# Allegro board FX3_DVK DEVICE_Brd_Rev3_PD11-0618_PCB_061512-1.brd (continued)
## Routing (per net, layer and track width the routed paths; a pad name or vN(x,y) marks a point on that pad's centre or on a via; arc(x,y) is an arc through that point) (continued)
CTL1: length 73.1
  TOP w0.279: J77.51 7.57,68.83 7.52,68.78 v1(7.48,68.78)
  TOP w0.381: J1.23 v1(25.52,61.45)
  TOP w0.483: v1(50.44,63.28) 51.24,64.07 R222.2
  SIG1#3 w0.127: v1(7.48,68.78) 7.1,68.41 5.08,68.41 4.75,68.74 4.75,69.06 5,69.32 7.88,69.32 8.47,68.73 8.47,66.79 8.07,66.39 4.75,66.39 4.23,65.87 4.23,64.42 4.99,63.67 6.95,63.67 9.53,66.24 10.67,66.24 11.04,65.87 12.44,64.46 14.17,62.74 24.23,62.74 24.68,62.28 24.68,62.28 v1(25.52,61.45) 25.52,61.44 25.53,61.44 25.79,61.71 29.24,61.71 29.61,62.08 32.98,62.08 33.82,61.24 33.82,59.79 34.5,59.11 45.81,59.11 49.02,62.32 50.13,62.32 50.44,62.63 v1(50.44,63.28)
CTL2: length 71.7
  TOP w0.279: J77.55 7.74,67.83 7.55,68.02 v1(7.53,68.02)
  TOP w0.381: J1.25 23.91,60.81 23.61,61.11 v1(23.61,61.57)
  SIG1#3 w0.127: v1(7.53,68.02) 7.82,68.02 8.04,67.8 8.04,66.97 7.89,66.82 4.58,66.82 3.8,66.05 3.8,64.24 3.82,64.22 3.82,64.21 5.38,62.65 11.27,62.65 13.12,60.81 15.05,60.81 16.11,61.87 17.78,61.87 18.28,61.37 21.71,61.37 22.22,61.87 23.3,61.87 23.6,61.57 v1(23.61,61.57)
  SIG2#6 w0.127: v1(49.74,64.4) 49.81,64.4 49.81,64.41 50.41,64.41 50.9,63.92 50.9,62.6 50.63,62.33 48.79,62.33 47.49,63.63 34.64,63.63 32.27,66 32.27,66.45 31.01,67.71 30.03,67.71 29.13,66.81 29.13,66.8 29.08,66.75 29.08,64.85 28.51,64.28 26.9,64.28 26.01,63.39 26.01,62.58 25.39,61.96 25.39,61.95 24.9,61.46 23.72,61.46 v1(23.61,61.57)
  BOTTOM w0.483: R223.2 50.43,65.02 49.81,64.4 v1(49.74,64.4)
CTL3: length 70.6
  TOP w0.203: J77.31 8.95,73.84 v1(10.4,73.84)
  TOP w0.381: v1(25.37,66.53) J1.7
  TOP w0.483: v1(53.96,69.36) 54.1,69.22 R224.2
  SIG1#3 w0.127: v1(25.37,66.53) 25.37,66.53 24.33,67.57 24.33,74.87 23.75,75.45 21.39,75.45 20.81,74.87 20.81,69.22 19.15,67.57 16.3,67.57 16.23,67.63 15.87,67.63 10.4,73.1 v1(10.4,73.84)
  SIG2#6 w0.127: v1(25.37,66.53) 25.37,66.59 24.73,67.23 24.73,69.08 26.15,70.51 26.39,70.51 26.39,70.51 29.66,70.51 29.75,70.42 34.07,70.42 36.55,67.94 42.81,67.94 43.33,67.42 48.06,67.42 49.17,68.53 51.08,68.53 52.09,69.54 52.61,69.54 52.98,69.54 53.16,69.36 v1(53.96,69.36)
CTL4: length 24.5
  TOP w0.203: v1(13.3,66.82) 13.31,66.83 J77.60
  SIG2#6 w0.127: J100.1 16.66,75.4 16.53,75.2 15.67,73.22 13.3,66.8 v1(13.3,66.82)
CTL4_LT: length 10.2
  TOP w0.483: J100.3 23.08,91.95 19.4,95.63 U45.3
CTL4_SW: length 49.3
  TOP w0.381: v1(34.44,66.9) 34.44,66.55 32.51,64.62 J1.14
  TOP w0.483: v1(54.01,65.28) 54.39,65.28 54.77,65.66 R225.2
  SIG1#3 w0.127: J100.2 25.66,87.29 v1(34.44,66.9)
  SIG2#6 w0.127: v1(54.01,65.28) 54,65.27 53.46,65.27 53.05,65.29 50.7,66.17 49.78,66.31 49.53,66.32 v1(34.44,66.9)
CTL5: length 68.5
  TOP w0.279: v1(11.08,70.77) 11.07,70.78 11.07,70.97 10.69,71.35 10.69,71.38 10.23,71.83 J77.39
  TOP w0.381: J1.13 23.59,64.62 v1(23.45,64.76)
  TOP w0.483: v1(49.82,69.55) 49.87,69.6 R226.2
  SIG1#3 w0.127: v1(11.08,70.77) 11.22,70.77 13.07,68.92 13.07,68.91 13.34,68.65 13.34,68.65 16.61,65.39 19.36,65.39 21.67,67.69 21.67,73.35 22.06,73.75 23.1,73.75 23.45,73.4 v1(23.45,64.76)
  SIG2#6 w0.127: v1(49.82,69.55) 49.58,69.55 49.41,69.38 47.89,67.86 43.51,67.86 42.99,68.37 36.73,68.37 34.25,70.85 29.93,70.85 29.84,70.95 26.21,70.95 26.21,70.94 25.97,70.94 24.19,69.16 24.19,68.73 24.19,67.3 23.45,66.56 v1(23.45,64.76)
CTL6: length 72.5
  TOP w0.279: J77.45 v1(7.48,70.33)
  TOP w0.381: J1.19 v1(25.52,62.72)
  TOP w0.483: v1(50.55,65.73) 50.89,65.73 51.2,66.04 R227.2
  SIG1#3 w0.127: v1(50.55,65.73) 50.55,64.58 49.58,63.62 48.79,63.62 45.88,60.71 45.28,60.71 34.96,60.71 33.16,62.51 30.69,62.51 29.5,63.7 27.5,63.7 26.51,62.72 v1(25.52,62.72) 24.86,62.72 24.41,63.17 14.35,63.17 12.91,64.6 12.91,64.61 10.79,66.73 10.79,66.73 9.98,67.54 8.9,68.62 8.9,68.91 8.29,69.52 8.06,69.75 3.07,69.75 1.76,71.07 1.76,74.43 2.21,74.88 3.63,74.88 4.14,74.37 4.14,72.16 5.19,71.11 6.7,71.11 v1(7.48,70.33)
CTL7: length 71.4
  TOP w0.279: J77.37 10.45,72.33 11.21,71.58 v1(11.21,71.58)
  TOP w0.381: v1(25.82,64.79) 25.35,65.26 J1.11
  SIG1#3 w0.127: v1(25.82,64.79) 25.82,64.75 25.53,64.46 24.28,64.46 23.89,64.85 23.89,74.67 23.58,74.99 21.54,74.99 21.24,74.69 21.24,67.87 19.19,65.82 16.81,65.82 15.62,67 15.62,67 11.22,71.4 11.22,71.57 v1(11.21,71.58)
  SIG2#6 w0.127: v1(25.82,64.79) 26.07,64.54 26.55,64.54 27.1,65.09 27.1,68.29 27.59,68.77 28.51,68.77 29.14,68.14 30.83,68.14 31.19,68.14 31.95,67.39 31.95,67.39 32.7,66.63 32.7,66.18 34.07,64.81 48.01,64.81 49.97,62.85 v1(49.97,62.79)
  BOTTOM w0.483: v1(49.97,62.79) 50.1,62.65 50.7,62.65 51.24,63.19 R228.2
CTL8: length 62.6
  TOP w0.279: v1(9.97,65.78) 10.44,66.25 10.44,69 10.1,69.34 9.2,69.34 9.2,69.33 J77.49
  TOP w0.381: v1(27.18,61.22) 27.09,61.32 27.05,61.32 26.29,62.08 J1.21
  SIG1#3 w0.127: v1(9.97,65.78) 9.97,65.78 9.28,65.09 9.28,63.8 9.99,63.09 11.45,63.09 12.23,62.3 23.12,62.3 23.51,62.3 24.06,61.76 24.82,60.99 26.95,60.99 v1(27.18,61.22)
  SIG2#6 w0.127: v1(50.33,54.74) 50.33,54.05 49.91,53.62 48.13,53.62 47.49,54.26 47.49,55.68 49.14,57.33 49.14,58.34 48.96,58.53 47.44,58.53 45.1,60.87 33.06,60.87 32.85,60.66 31.71,60.66 30.96,61.4 28.79,61.4 28.61,61.22 v1(27.18,61.22)
  BOTTOM w0.483: R229.2 v1(50.33,54.74)
CTL9: length 73.6
  TOP w0.279: J77.41 10.1,71.33 10.35,71.08 10.35,70.51 10.4,70.47 10.4,70.37 v1(10.42,70.35)
  TOP w0.381: J1.15 v1(25.52,63.99)
  TOP w0.483: R230.2 54.52,67.16 v1(54.14,67.16)
  SIG1#3 w0.127: v1(54.14,67.16) 54.14,67.02 53.36,66.24 52.26,66.24 51.35,67.15 50.37,67.15 50.37,67.16 50,67.16 49.99,67.15 49.98,67.15 49.71,66.88 49.71,66.33 44.96,61.57 44.92,61.57 44.6,61.57 35.41,61.57 33.54,63.44 31.01,63.44 30.07,64.38 29.1,65.35 29.1,65.71 28.56,66.25 26.8,66.25 26.39,65.84 26.39,64.71 25.67,63.99 v1(25.52,63.99) 25.5,63.99 25.46,64.03 14.72,64.03 11.08,67.67 11.07,67.67 10.59,68.15 9.77,68.98 9.77,69.27 8.71,70.32 8.71,72.37 7.43,73.66 7.43,75.97 7.75,76.29 8.64,76.29 9.3,75.63 9.3,75.63 9.96,74.97 9.96,70.81 v1(10.42,70.35)
CTL10: length 72.5
  TOP w0.279: J77.43 7.7,70.83 v1(7.46,71.07)
  TOP w0.381: J1.17 v1(25.56,63.35)
  TOP w0.483: R231.2 51.08,67.82 50.52,67.26 50.52,67.26 50.19,66.93 50.19,66.92 50.18,66.91 v1(50.18,66.71)
  SIG1#3 w0.127: v1(7.46,71.07) 7.46,71.08 6.99,71.55 5.56,71.55 4.57,72.53 4.57,77.29 5.08,77.8 6.52,77.8 7,77.32 7,73.48 8.28,72.19 8.28,70.14 9.33,69.09 9.33,68.8 10.29,67.85 10.64,67.49 11.04,67.09 14.53,63.6 24.59,63.6 24.83,63.35 v1(25.56,63.35) 26.53,63.35 27.32,64.14 29.7,64.14 29.89,63.94 30.9,62.94 33.34,62.94 35.14,61.14 44.42,61.14 45.22,61.14 48.94,64.85 49.55,64.85 50.1,65.4 50.1,66.63 v1(50.18,66.71)
CTL11: length 73
  TOP w0.279: J77.54 15.93,68.33 v1(16.04,68.44)
  TOP w0.381: v1(32.44,63.88) 32.34,63.99 J1.16
  SIG1#3 w0.127: v1(54.09,68.05) 53.88,67.85 53.39,67.35 51.69,67.35 51.51,67.53 50.53,67.53 50.52,67.54 49.84,67.54 49.84,67.53 49.83,67.53 49.33,67.04 49.33,66.72 49.33,66.56 44.96,62.19 36.6,62.19 35.48,63.31 35.48,64.38 34.68,65.18 33.06,65.18 32.44,64.56 v1(32.44,63.88) 31.2,63.88 29.53,65.55 29.53,66.02 29.42,66.13 28.87,66.68 25.93,66.68 25.61,67 25.61,67 25.35,67.26 25.35,67.26 24.8,67.82 24.8,77.28 22.25,79.83 18.92,79.83 17.77,78.67 17.77,76.12 20.37,73.52 20.37,69.43 19.6,68.66 16.28,68.66 16.06,68.44 v1(16.04,68.44)
  BOTTOM w0.483: v1(54.09,68.05) 54.36,68.33 R232.2
CTL12: length 70.6
  TOP w0.279: J77.57 7.5,67.33 v1(7.48,67.35)
  TOP w0.381: v1(22.52,61.34) 22.53,61.33 22.53,61.33 23.69,60.18 J1.27
  SIG1#3 w0.127: v1(22.52,61.34) 22.52,61.32 21.57,60.37 12.94,60.37 11.09,62.22 5.17,62.22 3.32,64.07 3.32,66.35 4.71,67.75 7.09,67.75 v1(7.48,67.35)
  SIG2#6 w0.127: v1(49.52,65.48) 49.52,65.48 49.29,65.24 34.25,65.24 33.13,66.36 33.13,66.81 32.38,67.56 32.38,67.57 31.37,68.58 31.37,68.58 30.65,68.58 30.65,68.58 29.7,68.58 29.06,69.22 27.08,69.22 26.67,68.81 26.67,66.29 22.52,62.14 v1(22.52,61.34)
  BOTTOM w0.483: v1(49.52,65.48) 49.52,67.08 49.54,67.09 49.54,67.11 51.14,68.71 R233.2
CVDDQ: length 4.9
  TOP w0.254: U1.B6 68,62.71 68,62.71 v2(68.24,62.95) ; X2.12 v1(75.44,54.38)
  TOP w0.508: R39.2 v3(74.04,75.82) ; R63.2 v3(11.1,106.35) ; R37.2 v3(69.72,75.82) ; R38.2 v3(71.75,75.82) ; R10.2 v3(9.47,101.8)
DQ0: length 67.8
  TOP w0.254: v1(13.29,59.91) 13.37,59.83 J77.68
  TOP w0.381: v1(23.01,59.46) 23.09,59.54 J1.29
  SIG1#3 w0.127: v1(49.97,55.69) 48.82,54.54 33.89,54.54 33.29,55.14 28.89,55.14 28.12,54.37 25.55,54.37 24.81,55.11 24.81,58.12 23.47,59.46 v1(23.01,59.46) 16.91,59.46 16.77,59.6 15.95,59.6 15.61,59.26 15.61,58 15.96,57.65 15.96,57.65 16.22,57.39 16.22,57.39 16.38,57.23 20.46,57.23 21.22,56.47 21.22,54.41 20.19,53.39 14.71,53.39 13.71,54.39 13.71,59.5 v1(13.29,59.91)
  BOTTOM w0.483: v1(49.97,55.69) 50.17,55.69 51.24,56.76 R5.2
DQ1: length 67
  TOP w0.254: v1(16.89,58.33) 16.88,58.34 14.68,58.34 J77.74
  TOP w0.381: v1(29.74,60.92) 29.74,61.16 29.74,61.16 29.74,62.31 30.78,63.35 J1.18
  SIG1#3 w0.127: v1(29.74,60.92) 29.74,60.91 29.74,59.35 29.01,58.61 26.37,58.61 25.54,57.78 25.54,56.46 26.38,55.63 33.41,55.63 34.07,54.97 48.54,54.97 49.71,56.14 50.41,56.14 50.78,55.77 50.78,55.06 51.11,54.72 52.29,54.72 52.62,55.05 52.62,58.52 52.14,59 50.98,59 50.53,58.56 50.53,57.13 v1(50.44,57.03)
  SIG2#6 w0.127: v1(16.89,58.33) 17.47,57.76 21.71,57.76 22.45,57.02 25.8,57.02 27.67,58.89 28.26,58.89 29.74,60.37 v1(29.74,60.92)
  BOTTOM w0.483: v1(50.44,57.03) 50.44,57.15 51.08,57.78 R205.2
DQ2: length 71.5
  TOP w0.254: J77.76 v1(16.4,57.83)
  TOP w0.381: v1(30.32,60.95) 30.32,60.96 30.32,62.06 30.97,62.72 J1.20
  TOP w0.483: R206.2 54.66,60.33 53.89,59.55 v1(53.84,59.55)
  SIG1#3 w0.127: v1(53.84,59.55) 49.41,59.55 49.04,59.18 49.04,59.17 47.34,57.47 47.34,57.46 46.93,57.05 46.92,57.05 46.22,56.35 34.02,56.35 33.37,57 33.35,57 33.34,57.01 32.95,57.01 32,56.06 29.39,56.06 29.08,56.37 29.08,57.23 29.08,57.23 29.08,58 29.46,58.38 30.17,58.38 30.49,58.06 30.49,57.01 30.72,56.77 31.4,56.77 31.66,57.03 31.66,57.79 31.81,57.94 32.7,57.94 33.05,58.28 33.05,58.82 32.76,59.11 30.45,59.11 30.19,59.37 30.19,59.83 30.44,60.07 32.44,60.07 32.72,60.36 32.72,60.75 32.46,61.01 30.48,61.01 30.42,60.95 v1(30.32,60.95)
  SIG2#6 w0.127: v1(30.32,60.95) 30.32,60.95 30.8,60.95 31.41,60.34 31.41,60.05 31.06,59.69 29.67,59.69 29.43,59.45 29.43,59.04 29.62,58.85 30.26,58.85 30.37,58.74 30.37,58.26 28.71,56.59 22.27,56.59 21.53,57.33 19.85,57.33 19.85,57.33 16.91,57.33 16.42,57.82 16.41,57.82 v1(16.4,57.83)
DQ3: length 73.3
  TOP w0.254: v1(16.15,59.14) 15.95,59.33 J77.70
  TOP w0.381: J1.31 23.26,58.91 23.25,58.89 22.97,58.89 v1(22.95,58.86)
  SIG1#3 w0.127: v1(54.79,55.87) 54.79,55.33 53.84,54.38 52.99,54.38 52.72,54.11 33.71,54.11 33.11,54.71 29.09,54.71 28.31,53.93 26.41,53.93 26,53.53 26,51.9 26.35,51.55 33.29,51.55 33.6,51.25 33.6,49.62 33.28,49.31 24.87,49.31 24.28,49.9 24.28,57.84 23.26,58.86 v1(22.95,58.86) 20.01,58.86 19.29,58.13 18.02,58.13 17.13,59.03 16.73,59.03 16.26,59.03 v1(16.15,59.14)
  BOTTOM w0.483: v1(54.79,55.87) R207.2
DQ4: length 68.3
  TOP w0.279: v1(16.05,69.33) J77.50
  TOP w0.381: v1(30.66,65.14) 30.75,65.23 31,65.23 31.02,65.26 J1.12
  TOP w0.483: v1(50.08,57.69) 50.3,57.69 51.24,58.63 R208.2
  SIG1#3 w0.127: v1(30.66,65.14) 30.58,65.14 29.96,65.76 29.96,68.38 29.49,68.85 29.49,68.87 29.26,69.1 29.26,69.1 25.85,72.51 25.85,77.64 24.08,79.4 22.8,80.69 17.87,80.69 15.81,78.63 15.81,75 17.11,73.7 18.05,73.7 18.98,72.78 18.98,71.53 17.9,70.45 17.17,70.45 16.05,69.34 v1(16.05,69.33)
  SIG2#6 w0.127: v1(30.66,65.14) 30.66,62.45 32.02,61.09 32.67,61.09 32.92,61.33 45.25,61.33 47.62,58.96 49.63,58.96 50.1,58.49 50.1,58.07 50.08,58.05 v1(50.08,57.69)
DQ5: length 67.7
  TOP w0.254: J77.80 17.67,56.83 v1(18.06,56.45)
  TOP w0.381: v1(34.32,60.04) 34.32,60.03 34.13,59.84 33.07,59.84 32.73,60.18 J1.28
  SIG1#3 w0.127: v1(50.81,66.7) 51.11,66.4 51.11,64.6 49.71,63.2 48.98,63.2 45.4,59.62 34.74,59.62 v1(34.32,60.04)
  SIG2#6 w0.127: v1(18.06,56.45) 18.04,56.46 14.3,56.46 14.09,56.26 14.09,55.5 15.67,53.92 16.56,53.92 16.81,54.17 16.81,55.17 17.06,55.43 18.12,55.43 18.4,55.15 18.4,53.08 18.64,52.84 19.65,52.84 19.88,53.06 19.88,56.13 20.21,56.46 21.17,56.46 21.49,56.15 21.49,53.35 21.87,52.98 22.94,52.98 23.61,53.65 23.61,55.37 23.96,55.73 29.06,55.73 31.93,58.59 32.43,59.1 32.44,59.1 33.07,59.72 33.93,59.72 34.25,60.04 v1(34.32,60.04)
  BOTTOM w0.483: R209.2 51.04,66.93 50.82,66.71 50.81,66.71 50.81,66.7 v1(50.81,66.7)
DQ6: length 75.6
  TOP w0.254: J77.32 17.43,73.83 18.33,72.93 18.33,72.19 v1(18.1,71.95)
  TOP w0.381: v1(30.55,66.33) 30.74,66.53 J1.8
  SIG1#3 w0.127: v1(18.1,71.95) 16.37,71.95 13.51,74.81 13.51,79.33 16.31,82.13 22.58,82.13 30.18,74.53 30.18,69.77 30.56,69.39 30.56,66.34 v1(30.55,66.33)
  SIG2#6 w0.127: v1(54.1,57.64) 54.11,57.64 54.11,58.43 53.81,58.72 53.38,58.72 53.27,58.62 52.77,58.62 50.85,60.53 48.76,60.53 47.04,62.24 33.15,62.24 31.1,64.3 31.1,65.33 30.55,65.89 v1(30.55,66.33)
  BOTTOM w0.483: v1(54.1,57.64) 54.1,57.88 54.32,58.1 54.32,58.1 54.64,58.42 R210.2
DQ7: length 71.4
  TOP w0.203: v1(17.56,70.9) 17.54,70.9 17.44,71 17.44,71 17.1,71.33 J77.42
  TOP w0.381: v1(29.93,69.04) 29.93,66.1 30.26,65.78 30.29,65.78 30.31,65.75 30.78,65.75 30.92,65.89 J1.10
  TOP w0.483: R211.2 51.2,62.36 50.72,61.87 v1(50.43,61.87)
  SIG1#3 w0.127: v1(17.56,70.9) 17.73,70.9 18.54,71.71 18.54,72.6 17.87,73.27 16.43,73.27 15.14,74.57 15.14,78.78 17.48,81.12 22.98,81.12 26.28,77.82 26.28,72.69 27.27,71.71 27.27,71.71 29.93,69.05 v1(29.93,69.04)
  SIG2#6 w0.127: v1(29.93,69.04) 32.75,69.04 33.56,68.23 33.56,66.54 34.18,65.92 34.18,65.92 34.43,65.67 41.06,65.67 41.31,65.92 49.71,65.92 49.87,65.76 49.87,65.76 50.72,64.91 50.72,64.9 51.66,63.97 51.66,62.27 51.26,61.87 v1(50.43,61.87)
DQ8: length 75.7
  TOP w0.254: J77.66 16.02,60.33 16.04,60.32 16.68,60.32 v1(17.09,59.91)
  TOP w0.381: J1.24 32.25,61.45 v1(32.35,61.54)
  SIG1#3 w0.127: v1(32.35,61.54) 32.35,61.44 29.63,61.44 29.08,60.89 29.08,59.5 28.63,59.04 26.09,59.04 24.86,60.28 23.52,60.28 23.18,59.94 17.13,59.94 v1(17.09,59.91)
  SIG2#6 w0.127: v1(53.56,58.28) 52.6,57.32 52.6,49.68 50.04,47.11 47.06,47.11 45.44,48.74 45.44,52.37 46.31,53.24 50.6,53.24 50.99,53.63 50.99,58.79 50.39,59.39 48.17,59.39 45.75,61.81 32.62,61.81 32.35,61.54 v1(32.35,61.54)
  BOTTOM w0.483: v1(53.56,58.28) 53.56,58.37 54.25,59.06 54.26,59.06 54.32,59.11 54.32,59.11 54.64,59.44 R212.2
DQ9: length 70.4
  TOP w0.254: v1(10.42,54.33) J77.89
  TOP w0.381: J1.36 32.33,57.64 32.74,57.23 32.74,57.23 33.16,56.81 v1(33.16,56.57)
  SIG1#3 w0.127: v1(33.16,56.57) 33.19,56.57 33.92,55.84 47.25,55.84 49.66,58.24 v1(49.66,58.25)
  SIG2#6 w0.127: v1(33.16,56.57) 35.55,56.57 36.65,55.47 36.65,55.25 36.65,55.24 36.65,49.04 36.12,48.5 33.65,48.5 33.01,49.15 33.01,53.74 32,54.75 31.16,54.75 27.19,50.79 27.19,50.79 26.58,50.17 12.56,50.17 10.42,52.31 v1(10.42,54.33)
  BOTTOM w0.483: R213.2 51.15,59.56 49.87,58.29 49.75,58.29 49.71,58.25 v1(49.66,58.25)
DQ10: length 75.1
  TOP w0.254: J77.61 10.41,61.33 10.72,61.03 v1(10.72,61.03)
  TOP w0.381: v1(23.39,57.48) 23.39,57.89 23.77,58.27 J1.33
  TOP w0.483: v1(53.77,61.3) 53.98,61.3 54.78,62.1 R214.2
  SIG1#3 w0.127: v1(10.72,61.03) 11.14,60.6 11.14,59.01 13.28,56.88 13.28,54.21 15.33,52.15 21.67,52.15 23.25,53.73 23.25,53.73 23.34,53.82 23.34,57.4 23.4,57.46 23.4,57.48 v1(23.39,57.48)
  SIG2#6 w0.127: v1(23.39,57.48) 23.39,57.88 22.86,58.41 22.28,58.41 21.72,58.98 21.72,60.07 22.05,60.41 24.18,60.41 24.4,60.19 24.4,58.84 24.85,58.39 25.93,58.39 26.29,58.75 26.29,60.96 26.73,61.41 27,61.67 28.44,61.67 29.94,63.17 29.94,66.35 30.37,66.78 30.72,66.78 31.4,66.1 31.4,65.64 34.37,62.68 47.22,62.68 47.23,62.67 48.98,60.92 52.97,60.92 53.34,61.3 v1(53.77,61.3)
DQ11: length 75.6
  TOP w0.254: v1(11.01,56.28) 10.99,56.3 10.99,56.47 10.62,56.83 J77.79
  TOP w0.381: J1.30 32.63,59.54 32.85,59.32 33.66,59.32 34.51,58.47 v1(34.53,58.47)
  TOP w0.483: R215.2 54.66,63.88 54.26,63.48 v1(54.13,63.48)
  SIG1#3 w0.127: v1(54.13,63.48) 53.73,63.48 52.87,62.62 52.87,62.62 51.27,61.02 48.37,61.02 47.6,60.25 47.6,60.25 45.84,58.5 34.56,58.5 v1(34.53,58.47)
  SIG2#6 w0.127: v1(11.01,56.28) 11.01,56.27 11.3,55.98 11.3,52.65 12.41,51.54 26.35,51.54 26.36,51.54 26.72,51.54 30.8,55.62 30.8,55.63 32.97,57.8 32.98,57.8 33.09,57.91 33.12,57.91 33.12,57.91 33.49,57.91 33.49,57.91 34.05,57.91 34.06,57.91 34.42,57.91 34.43,57.91 35.47,57.91 36.18,57.2 36.18,57.19 37.52,55.86 37.52,55.5 37.52,53.59 37.87,53.23 39.38,53.23 39.78,53.63 39.78,55.61 36.75,58.64 34.7,58.64 v1(34.53,58.47)
DQ12: length 72.3
  TOP w0.254: J77.71 10.27,58.83 11.24,57.86 v1(11.24,57.38)
  TOP w0.381: J1.35 25.25,57.64 25.6,57.29 v1(25.6,55.19)
  TOP w0.483: v1(48.7,58.08) 48.71,58.1 48.71,58.16 51.1,60.55 51.21,60.55 R216.2
  SIG2#6 w0.127: v1(48.7,58.08) 48.54,57.92 48.54,57.91 44.23,53.6 44.23,46.7 43.59,46.06 41.94,46.06 41.27,46.72 41.27,55.34 37.07,59.54 34.37,59.54 33.83,59.01 32.97,59.01 32.62,58.66 32.61,58.66 29.14,55.19 v1(25.6,55.19) 25.6,55.03 22.98,52.41 16.57,52.41 12.1,56.87 12.1,56.91 11.62,57.38 v1(11.24,57.38)
DQ13: length 72.6
  TOP w0.254: v1(10.35,56.28) 10.35,56.28 10.29,56.33 J77.81
  TOP w0.381: J1.32 32.53,58.91 32.64,58.79 32.92,58.79 33.68,58.03 33.69,58.03 34.24,57.48 v1(34.24,57.47)
  SIG1#3 w0.127: v1(48.7,60.08) 48.7,60.07 45.9,57.27 34.45,57.27 34.25,57.47 v1(34.24,57.47)
  SIG2#6 w0.127: v1(34.24,57.47) 35.29,57.47 36,56.76 37.08,55.68 37.08,53.41 37.69,52.8 38.05,52.8 39.2,52.8 39.2,52.8 39.56,52.8 40.21,53.45 40.21,55.79 36.9,59.1 34.53,59.1 34.01,58.58 33.15,58.58 32.8,58.23 32.79,58.23 30.37,55.81 30.37,55.8 26.54,51.97 14.71,51.97 12.31,54.38 12.31,55.99 11.95,56.34 11.51,56.79 10.86,56.79 v1(10.35,56.28)
  BOTTOM w0.483: R217.2 51.23,61.47 49.85,60.08 48.7,60.08 v1(48.7,60.08)
DQ14: length 75.6
  TOP w0.254: J77.65 10.26,60.33 10.44,60.51 v1(10.45,60.51)
  TOP w0.381: J1.37 23.81,57 23.72,56.91 23.15,56.91 22.75,57.32 v1(22.75,57.9)
  SIG1#3 w0.127: v1(22.75,57.9) 22.88,58.03 23.48,58.03 23.84,57.66 23.84,53.72 23.68,53.55 23.68,53.55 21.85,51.72 14.98,51.72 12.57,54.13 12.57,56.89 10.53,58.93 10.53,58.93 9.95,59.51 9.95,60.06 10.4,60.51 v1(10.45,60.51)
  SIG2#6 w0.127: v1(53.9,62.59) 53.83,62.65 53.02,62.65 51.67,61.31 49.2,61.31 47.38,63.13 34.53,63.13 31.84,65.82 31.84,66.28 30.9,67.21 30.54,67.21 30.54,67.21 30.14,67.21 29.51,66.58 29.51,64.67 29.5,64.66 29.5,64.56 28.78,63.85 28.69,63.85 27.08,63.85 26.44,63.21 26.44,61.73 26.3,61.59 26.3,61.59 26.29,61.57 25.62,60.9 21.93,60.9 21.07,60.04 21.07,59.01 21.89,58.19 21.89,58.19 22.18,57.9 v1(22.75,57.9)
  BOTTOM w0.483: R218.2 54.39,62.59 v1(53.9,62.59)
DQ15: length 73.9
  TOP w0.254: J77.83 10.11,55.83 10.25,55.68 v1(10.34,55.68)
  TOP w0.381: v1(33.31,57.47) 33.29,57.47 32.49,58.27 J1.34
  SIG1#3 w0.127: v1(53.9,60.41) 53.42,59.93 52.78,59.93 52.78,59.93 49.18,59.93 48.61,59.36 48.61,59.35 46.04,56.78 34.2,56.78 33.52,57.46 33.32,57.46 v1(33.31,57.47)
  SIG2#6 w0.127: v1(33.31,57.47) 33.3,57.47 33.21,57.39 33.21,57.39 32.69,56.87 32.69,56.2 32.99,55.9 35.61,55.9 36.22,55.29 36.22,49.85 35.87,49.5 33.69,49.5 33.44,49.75 33.44,53.92 32.17,55.19 30.98,55.19 26.9,51.11 26.18,51.11 12.23,51.11 10.87,52.48 10.87,55.18 10.36,55.68 v1(10.34,55.68)
  BOTTOM w0.483: v1(53.9,60.41) 54.7,61.21 R219.2
DQ16: length 73
  TOP w0.254: v1(16.48,68.01) 16.45,68.01 16.27,67.83 J77.56
  TOP w0.381: v1(42.28,76.47) J2.11
  SIG2#6 w0.127: v1(16.48,68.01) 16.76,68.01 18.57,69.81 18.57,72.66 25.64,79.74 27.93,79.74 28.3,80.11 28.3,82.52 29.08,83.3 30.44,83.3 31.07,82.67 31.07,79.41 31.33,79.16 32.85,79.16 33.11,79.42 33.11,83.52 33.42,83.82 34.15,83.82 34.54,83.43 34.54,79.45 34.83,79.16 35.89,79.16 36.16,79.43 36.16,82.06 36.39,82.29 37.13,82.29 37.82,81.61 37.82,78.26 39.84,76.23 42.04,76.23 v1(42.28,76.47) 43.07,75.68 43.07,74.33 44.21,73.19 44.58,72.83 50.52,72.83 50.69,72.66 53.79,72.66 v1(53.97,72.83)
  BOTTOM w0.483: v1(53.97,72.83) 54,72.8 54,72.78 54.79,71.98 R6.2
DQ17: length 72.5
  TOP w0.254: J77.85 7.52,55.33 v1(7.42,55.43)
  TOP w0.381: v1(38.71,71.24) 38.86,71.39 J2.27
  SIG1#3 w0.127: v1(38.71,71.24) 38.44,70.96 38.44,69.41 42.71,65.14 45.8,65.14 46.66,66 47.51,66.85 47.52,66.85 47.77,67.1 47.78,67.1 49.35,68.68 49.35,68.68 51.64,68.68 52.51,69.54 53.19,69.54 53.7,70.05 v1(53.7,70.28)
  SIG2#6 w0.127: v1(7.42,55.43) 7.3,55.55 7.3,55.89 7.57,56.16 7.87,56.16 11.18,59.46 11.18,60.8 11.68,61.3 15.14,61.3 17.34,63.5 21.2,67.35 21.2,67.36 22.03,68.19 22.03,71.23 27.02,76.22 28.95,76.22 29.46,75.71 29.47,75.71 30.13,75.04 30.13,73.7 30.82,73.01 36,73.01 37.78,71.24 v1(38.71,71.24)
  BOTTOM w0.483: v1(53.7,70.28) 53.87,70.1 R12.2
DQ18: length 73.4
  TOP w0.254: J77.73 7.81,58.33 7.64,58.5 v1(7.04,58.5)
  TOP w0.381: J2.19 42.23,73.93 v1(42.45,73.71)
  TOP w0.483: R13.2 54.79,72.75 54.25,72.21 v1(53.55,72.21)
  SIG2#6 w0.127: v1(7.04,58.5) 7.21,58.5 8,59.3 8,61.84 11.08,64.92 16.13,64.92 18.71,67.49 20,68.78 20,68.79 20.3,69.09 20.3,71.95 26.3,77.95 30.08,77.95 30.59,77.44 30.61,77.44 30.61,77.43 35,77.43 37.98,74.46 40.03,74.46 40.04,74.46 40.4,74.46 41.71,74.46 v1(42.45,73.71) 42.47,73.69 42.47,71.71 44.35,69.83 45.76,69.83 46.09,70.17 46.09,71.73 46.32,71.96 47,71.96 47.24,71.73 47.24,69.17 47.66,68.74 48.23,68.74 49.03,69.54 49.03,70.39 49.36,70.71 50.97,70.71 52.48,72.22 53.54,72.22 v1(53.55,72.21)
DQ19: length 70.6
  TOP w0.254: J77.87 v1(7.37,54.83)
  TOP w0.381: J2.29 40.13,70.75 v1(39.97,70.59)
  SIG1#3 w0.127: v1(54.17,74.72) 53.21,73.76 52.9,73.76 52.3,73.17 52.3,71.01 52.08,70.78 52.07,70.78 51.28,69.99 49.44,69.99 47.16,67.71 47.15,67.71 46.3,66.87 46.3,66.87 45.99,66.56 43.62,66.56 39.97,70.21 v1(39.97,70.59)
  SIG2#6 w0.127: v1(7.37,54.83) 7.46,54.83 7.87,55.24 7.87,55.54 11.72,59.39 13.82,59.39 15.12,60.69 15.14,60.69 15.39,60.94 15.39,60.94 17.77,63.32 21.63,67.18 21.63,67.18 22.46,68.01 22.46,68.37 22.46,70.93 25.81,74.28 25.81,74.29 27.32,75.79 28.77,75.79 29.28,75.27 29.28,75.27 29.7,74.85 29.7,73.52 30.65,72.58 35.56,72.58 37.56,70.58 39.85,70.58 39.87,70.59 v1(39.97,70.59)
  BOTTOM w0.483: R14.2 54.34,74.55 v1(54.17,74.72)
DQ20: length 69.8
  TOP w0.254: J77.77 7.41,57.33 7.39,57.35 v1(7.37,57.35)
  TOP w0.381: J2.23 42.1,72.66 43.3,71.46 v1(43.3,70.2)
  SIG1#3 w0.127: v1(43.3,70.2) 43.3,70.19 43.85,69.64 43.85,68.42 44.4,67.87 45.33,67.87 45.9,68.44 45.9,68.45 48.67,71.22 49.6,71.22 v1(49.74,71.36)
  SIG2#6 w0.127: v1(7.37,57.35) 7.37,57.35 8.92,58.9 8.92,61 10.66,62.75 15.37,62.75 16.48,63.86 19.54,66.92 19.54,66.92 21.16,68.55 21.16,71.59 26.66,77.09 29.72,77.09 30.23,76.57 30.25,76.57 30.25,76.57 34.58,76.57 37.57,73.58 38.65,73.58 38.94,73.29 38.94,72.46 39.25,72.15 39.86,72.15 40.21,72.5 40.21,73.08 40.66,73.53 41.5,73.53 42.04,72.99 42.04,71.46 v1(43.3,70.2)
  BOTTOM w0.483: R15.2 51.22,70.5 50.12,70.5 49.74,70.89 v1(49.74,71.36)
DQ21: length 70.5
  TOP w0.254: J77.75 7.61,57.83 7.52,57.92 v1(7.06,57.92)
  TOP w0.381: v1(40.22,74.01) 40.22,73.8 40.72,73.29 J2.21
  SIG1#3 w0.127: v1(40.22,74.01) 40.25,73.98 41.11,73.98 41.65,74.53 42.52,74.53 42.9,74.15 42.9,73.55 43.11,73.34 43.74,73.34 43.94,73.54 43.94,74.65 44.26,74.97 45.27,74.97 45.77,74.47 45.91,74.34 45.91,74.33 46.88,73.35 48.13,73.35 49.63,74.85 49.63,75.57 49.63,75.57 49.63,76.96 49.97,77.3 51.21,77.3 52.19,76.57 52.49,76.49 52.59,76.44 v1(53.87,76.1)
  SIG2#6 w0.127: v1(40.22,74.01) 37.81,74.01 34.82,77 30.43,77 30.43,77 30.41,77 29.9,77.52 26.48,77.52 20.73,71.77 20.73,68.91 20.43,68.61 20.43,68.6 19.14,67.31 15.15,63.33 10.1,63.33 8.49,61.71 8.49,59.17 7.24,57.92 v1(7.06,57.92)
  BOTTOM w0.483: v1(53.87,76.1) 54.41,75.56 R16.2
DQ22: length 68.4
  TOP w0.254: v1(7.4,59.33) 7.66,59.33 J77.69
  TOP w0.381: v1(40.43,74.9) 40.43,74.85 40.72,74.56 J2.17
  SIG2#6 w0.127: v1(50.63,72.11) 50.34,72.39 44.4,72.39 43.73,73.06 43.73,73.06 42.9,73.89 42.9,73.9 42.64,74.15 42.64,74.16 41.9,74.9 v1(40.43,74.9) 38.32,74.9 35.36,77.86 35.19,77.86 35.18,77.86 30.79,77.86 30.79,77.87 30.77,77.87 30.23,78.4 26.14,78.4 19.87,72.13 19.87,69.27 18.27,67.68 18.27,67.67 15.95,65.35 11.75,65.35 11.09,65.35 11.09,65.35 10.9,65.35 7.4,61.85 7.4,60.65 6.99,60.24 6.03,60.24 5.8,60.46 5.8,60.95 5.36,61.39 4.44,61.39 4,60.95 4,59.79 4.74,59.05 7.12,59.05 v1(7.4,59.33)
  BOTTOM w0.483: v1(50.63,72.11) 50.76,72.24 51.21,72.24 R17.2
DQ23: length 68
  TOP w0.254: v1(10.46,59.83) 10.45,59.83 8.95,59.83 J77.67
  TOP w0.381: v1(40.62,71.96) 40.68,72.02 J2.25
  TOP w0.483: v1(50.45,71.36) 50.53,71.36 50.55,71.37 R18.2
  SIG1#3 w0.127: v1(50.45,71.36) 50.44,71.36 49.99,71.8 49.23,71.8 49.04,71.62 48.19,71.62 46.4,69.83 44.31,69.83 43.43,70.71 41.34,70.71 40.62,71.43 v1(40.62,71.96)
  SIG2#6 w0.127: v1(10.46,59.83) 10.46,59.85 10.01,60.3 10.01,60.98 10.86,61.82 15.06,61.82 16.91,63.68 19.97,66.74 19.97,66.75 21.6,68.37 21.6,71.41 26.84,76.65 29.12,76.65 29.64,76.14 29.65,76.14 30.57,75.22 30.57,74.68 30.57,74.16 31.01,73.71 31.72,73.71 32.12,74.12 32.12,75.93 32.3,76.11 33.15,76.11 33.33,75.93 33.33,73.65 33.54,73.44 34.15,73.44 34.36,73.65 34.36,75.33 34.6,75.57 34.97,75.57 35.46,75.08 35.46,73.86 35.87,73.44 36.18,73.44 37.91,71.71 39.07,71.71 39.68,71.1 41.02,71.1 41.19,71.26 41.19,71.85 41.01,72.03 40.68,72.03 v1(40.62,71.96)
DQ24: length 64.7
  TOP w0.254: J77.78 14.68,57.33 17.73,57.33 v1(19.08,58.68)
  TOP w0.381: v1(40.96,66.2) 41.08,66.33 41.12,66.33 41.39,66.6 J2.37
  SIG1#3 w0.127: v1(40.96,66.2) 40.99,66.2 42.57,64.63 45.9,64.63 46.84,65.57 46.85,65.57 47.7,66.42 47.7,66.42 47.95,66.67 47.96,66.67 48.57,67.28 48.57,67.36 49.51,68.3 49.52,68.3 49.52,68.3 50.84,68.3 50.84,68.3 51.9,68.3 52.23,68.63 53.39,68.63 53.63,68.88 54.13,68.88 54.66,69.41 54.66,77.68 v1(53.99,78.35)
  SIG2#6 w0.127: v1(40.96,66.2) 40.84,66.2 34.51,66.2 34,66.72 34,68.05 34,68.43 32.95,69.48 29.47,69.48 29.3,69.65 26.81,69.65 26.24,69.08 26.24,68.44 26.24,66.48 23.44,63.67 23.44,63.67 19.08,59.31 v1(19.08,58.68)
  BOTTOM w0.483: R20.2 54.62,77.6 53.99,78.23 v1(53.99,78.35)
DQ25: length 66
  TOP w0.254: J77.72 12.5,58.83 v1(12.4,58.94)
  TOP w0.381: J2.35 v1(42.32,68.85)
  SIG1#3 w0.127: v1(50.45,73.9) 50.66,73.9 51.01,73.55 51.01,73.09 50.75,72.83 50.73,72.83 50.45,72.55 50.45,72.55 50.19,72.29 50.18,72.29 50.13,72.24 49.12,72.24 48.95,72.06 48.94,72.06 48.92,72.04 47.85,72.04 46.12,70.31 44.44,70.31 42.81,71.94 42.38,71.94 41.91,72.4 41.91,72.4 41.62,72.69 39.56,72.69 39.29,72.42 39.29,71.9 42.32,68.86 v1(42.32,68.85)
  SIG2#6 w0.127: v1(12.4,58.94) 12.4,58.92 13.03,58.29 14.56,58.29 15.02,58.75 15.02,59.9 15.32,60.2 16.31,60.2 16.51,60 16.51,59.53 17.19,58.85 18.02,58.85 18.67,59.5 18.67,59.51 23,63.85 23,66.73 23.75,67.48 23.75,68.55 23.75,68.91 23.75,69.78 25.6,71.63 29.76,71.63 30.11,71.28 34.62,71.28 37.06,68.85 v1(42.32,68.85)
  BOTTOM w0.483: v1(50.45,73.9) 50.48,73.9 50.62,74.04 R21.2
DQ26: length 66.9
  TOP w0.254: v1(6.91,60.83) 7.75,60.83 7.75,60.83 J77.63
  TOP w0.381: v1(42.22,75.21) 42.22,75.21 42.21,75.2 J2.15
  SIG1#3 w0.127: v1(42.22,75.21) 42.41,75.4 44.24,75.4 45.45,75.4 46.2,74.65 46.34,74.51 46.34,74.51 46.92,73.92 46.93,73.92 47.01,73.84 48.01,73.84 49.2,75.03 49.2,75.39 49.2,77.14 49.79,77.73 51.35,77.73 52.38,76.97 52.63,76.9 52.73,76.85 54.14,76.85 v1(54.14,76.85)
  SIG2#6 w0.127: v1(42.22,75.21) 42.1,75.34 40.62,75.34 40.62,75.34 40.25,75.34 40.25,75.34 38.59,75.34 35.63,78.3 30.97,78.3 30.96,78.3 30.95,78.3 30.37,78.88 28.57,78.88 28.57,78.88 26,78.88 19.44,72.31 19.44,69.45 17.84,67.85 17.71,67.72 17.71,67.72 17.2,67.21 17.19,67.21 16.73,66.75 16.73,66.74 16.22,66.23 9.73,66.23 6.91,63.41 v1(6.91,60.83)
  BOTTOM w0.483: v1(54.14,76.85) 54.41,76.58 R44.2
DQ27: length 63.5
  TOP w0.254: v1(16.07,67.19) 16,67.19 15.85,67.33 J77.58
  TOP w0.381: v1(40.18,75.78) 40.23,75.83 J2.13
  SIG1#3 w0.127: v1(53.9,79.4) 52.8,78.3 52.09,78.3 51.95,78.17 49.61,78.17 48.77,77.32 48.77,75.21 47.83,74.27 47.19,74.27 46.77,74.69 46.77,74.69 46.64,74.83 46.64,74.83 46.26,75.21 46.26,76.85 45.39,77.72 44.61,77.72 43.83,78.5 43.83,79.39 43.3,79.91 41.49,79.91 40.87,79.29 40.87,76.47 40.18,75.79 v1(40.18,75.78)
  SIG2#6 w0.127: v1(16.07,67.19) 16.08,67.18 16.55,67.18 17.01,67.64 17.02,67.64 17.28,67.9 17.28,67.9 17.41,68.03 17.41,68.03 19,69.62 19,72.48 25.82,79.31 28.39,79.31 28.73,79.65 28.73,79.93 28.73,80.78 29.06,81.11 30.34,81.11 30.64,80.81 30.64,79.59 30.64,79.59 30.64,79.22 31.13,78.73 31.14,78.73 31.15,78.73 33.03,78.73 33.03,78.73 35.82,78.73 38.77,75.78 v1(40.18,75.78)
  BOTTOM w0.483: R45.2 54.71,78.61 53.96,79.37 53.93,79.37 v1(53.9,79.4)
DQ28: length 63.6
  TOP w0.254: J77.38 17.48,72.33 17.8,72.65 v1(17.82,72.65)
  TOP w0.381: J2.7 39.68,77.74 39.68,77.74 v1(39.54,77.74)
  SIG2#6 w0.127: v1(17.82,72.65) 17.82,72.68 25.31,80.17 27.4,80.17 27.87,80.64 27.87,82.8 28.91,83.83 30.62,83.83 31.5,82.95 31.5,81.11 31.84,80.77 32.36,80.77 32.63,81.05 32.63,83.65 33.24,84.25 35.78,84.25 39.54,80.5 v1(39.54,77.74) 39.54,77.28 40.13,76.68 41.79,76.68 42.97,77.86 45.86,77.86 46.6,77.12 46.6,73.63 46.97,73.26 49.18,73.26 50.01,74.08 50.01,74.08 50.32,74.39 51.36,74.39 52,73.76 53.91,73.76 53.91,73.77 v1(53.95,73.77)
  BOTTOM w0.483: R49.2 54.21,73.53 54,73.72 53.99,73.73 v1(53.95,73.77)
DQ29: length 58.8
  TOP w0.254: v1(16.51,61.35) 16.46,61.35 16.45,61.33 J77.62
  TOP w0.381: v1(42.97,68.92) 42.97,69.71 42.57,70.12 J2.31
  SIG1#3 w0.127: v1(42.97,68.92) 42.88,68.82 42.88,67.92 43.79,67.01 45.83,67.01 49.2,70.37 51.03,70.37 51.87,71.21 51.87,75.24 50.27,76.84 v1(50.13,76.84)
  SIG2#6 w0.127: v1(42.97,68.92) 42.97,69.53 42.38,70.12 37.07,70.12 35.05,72.15 30.47,72.15 30.07,72.54 25.3,72.54 22.89,70.14 22.89,68.55 22.89,68.19 22.89,67.83 22.06,67 22.06,67 18.2,63.14 16.51,61.45 v1(16.51,61.35)
  BOTTOM w0.483: v1(50.13,76.84) 50.29,76.84 51.05,77.6 R50.2
DQ30: length 53.2
  TOP w0.254: J77.40 17.29,71.83 17.64,71.48 v1(17.64,71.48)
  TOP w0.381: v1(40.42,77.13) 40.48,77.13 40.51,77.1 J2.9
  SIG2#6 w0.127: v1(17.64,71.48) 17.34,71.78 17.34,73.05 28.99,84.7 36.2,84.7 39.98,80.93 39.98,77.57 40.38,77.17 40.39,77.17 v1(40.42,77.13) 41.56,77.13 43.42,79 43.42,79 46.05,81.63 v1(49.05,81.63)
  BOTTOM w0.483: v1(49.05,81.63) 49.05,81.63 49.05,80.8 49.57,80.28 49.57,80.28 50.38,79.47 50.38,79.47 R56.2
DQ31: length 57.2
  TOP w0.254: v1(16.24,60.83) 16.2,60.83 16.19,60.83 J77.64
  TOP w0.381: J2.33 42.36,69.48 v1(42.39,69.46)
  SIG1#3 w0.127: v1(42.39,69.46) 42.39,69.46 42.39,69.71 42.57,69.89 42.93,69.89 43.42,69.4 43.42,67.99 43.97,67.44 45.65,67.44 48.97,70.75 50.87,70.75 51.44,71.32 51.44,75.06 50.64,75.85 v1(50.09,75.85)
  SIG2#6 w0.127: v1(16.24,60.83) 16.28,60.79 19.03,60.79 22.57,64.33 22.57,66.91 23.32,67.66 23.32,68.37 23.32,68.37 23.32,68.73 23.32,68.73 23.32,69.96 25.43,72.06 29.94,72.06 30.29,71.72 34.8,71.72 37.22,69.3 42.23,69.3 v1(42.39,69.46)
  BOTTOM w0.483: v1(50.09,75.85) 50.19,75.95 50.62,75.95 51.01,76.34 51.01,76.35 R57.2
FAULTA_L: length 5.8
  TOP w0.33: R46.2 85.99,37.34 86.76,36.56 U8.10
  TOP w0.483: R46.2 85.54,40.32 TP28.1
FLAG: length 1.9
  TOP w0.508: R190.1 68.98,27.64 U37.4
FSLC0: length 11
  TOP w0.127: v2(68.24,66.15) 67.84,65.75 U1.B2
  TOP w0.483: v1(69.72,73.53) R37.1 R41.2
  SIG1#3 w0.127: v2(68.24,66.15) 68.25,66.15 68.64,66.54 68.64,67.99 69.01,68.37 69.01,68.42 70.61,70.01 70.61,71.87 69.71,72.77 69.71,73.52 v1(69.72,73.53)
FSLC1: length 14.3
  TOP w0.127: v2(68.24,64.55) 68.03,64.33 68.03,64.33 U1.B4
  TOP w0.483: v1(71.75,73.53) R38.1 R42.2
  SIG1#3 w0.127: v1(71.75,73.53) 71.75,73.53 71.75,72.79 72.64,71.9 72.64,67.5 69.69,64.55 v2(68.24,64.55)
FSLC2: length 18.6
  TOP w0.127: U1.E6 65.57,62.42 v2(65.84,62.15)
  TOP w0.483: v1(74.04,73.53) R39.1 R58.2
  SIG1#3 w0.127: v2(65.84,62.15) 66.25,62.55 68.81,62.55 73.07,66.82 73.07,66.82 74.04,67.79 v1(74.04,73.53)
GPIO45: length 61.6
  TOP w0.127: U1.F2 v2(64.24,66.15)
  TOP w0.305: v1(47.08,75.01) 47.06,75 47.06,74.45 47.36,74.15 47.37,74.15 47.59,73.93 J2.20
  SIG1#3 w0.127: v1(47.08,75.01) 47.08,75.02 47.06,75.04 47.06,75.09 46.69,75.46 46.69,75.78 46.69,75.78 46.69,78.77 39.89,85.58 39.89,94.07 35.95,98.01 TP13.1
  SIG2#6 w0.127: v2(64.24,66.15) 64.24,68.34 61.92,70.66 61.92,70.66 57.78,74.8 57.78,74.8 57.16,75.42 56.49,75.42 56.27,75.65 51.61,75.65 50.79,74.83 50.14,74.83 49.44,74.12 47.5,74.12 47.08,74.54 47.08,75.01 v1(47.08,75.01)
I2C_CHARGER_DETECT: length 14.5
  TOP w0.254: 66.24,57.76 U1.D11
  TOP w0.483: TP31.1 68.93,54.71 66.24,57.39 66.24,57.76
I2C_SCL_EEPROM: length 92.7
  TOP w0.127: J147.2 48.26,104.14 46.84,102.72 43.28,102.72 40.64,100.08 40.64,83.93 37.72,81.01 37.72,55.63 30.1,48.01 30.1,41.27 J42.1
  SIG2#6 w0.127: U44.6 48.26,105.61 J147.2
I2C_SCL_FX3: length 143
  TOP w0.127: v1(49.4,49.82) 49.4,52.7 47.24,54.86 47.24,68.96 47.77,69.48 J2.34 ; U1.D9 v2(66.64,59.75)
  SIG1#3 w0.127: v2(66.64,59.75) 66.67,59.75 67.05,59.38 67.05,58.68 67.6,58.12 67.6,56.05 68.26,55.39 68.26,51.14 66.94,49.82 v1(49.4,49.82) 47.53,47.95 26.25,47.95 24.55,46.25 24.55,43.28 26.67,41.16 26.67,38.61 J42.2
  SIG2#6 w0.127: v1(48.93,101.18) 48.94,101.19 49.01,101.19 49.09,101.27 49.15,101.22 51.18,101.22 54.17,98.23 58.36,98.23 68.07,88.52 68.07,72.8 68.59,72.29 68.59,70.24 67.84,69.49 67.84,63.59 67.61,63.35 67.28,63.35 67.05,63.12 67.05,60.14 66.66,59.75 v2(66.64,59.75)
  BOTTOM w0.483: v1(48.93,101.18) 48.88,101.22 R176.1
I2C_SCL_PPORT: length 81
  TOP w0.127: J2.26 47.39,72.02 46.35,70.99 46.35,61.59 32.38,47.62 32.38,36.45 30.35,34.42 J42.3 27.13,33.22 23.04,33.22 21.46,34.8 21.46,52.2 18.83,54.83 J77.88
I2C_SDA_EEPROM: length 98.9
  TOP w0.127: J147.3 49.63,105.57 44.34,105.57 40.01,101.23 40.01,84.14 37.21,81.35 37.21,56.13 27.05,45.97 27.05,42.42 J45.1
  SIG2#6 w0.127: U44.5 39.36,117.09 50.8,105.66 J147.3
I2C_SDA_FX3: length 136.7
  TOP w0.127: J2.32 47.64,70.12 46.86,69.34 46.86,54.61 48.64,52.83 v1(48.64,50.79) ; U1.D10 v2(66.64,58.95)
  SIG1#3 w0.127: v2(66.64,58.95) 66.64,55.66 67.42,54.88 67.42,51.67 66.55,50.79 v1(48.64,50.79) 46.33,48.48 26.13,48.48 24.11,46.46 24.11,42.79 25.34,41.56 25.34,39.01 24.13,37.8 J45.2
  SIG2#6 w0.127: v1(50.73,100.67) 54.87,96.53 57.26,96.53 67.56,86.23 67.56,70.23 67.05,69.72 67.05,63.6 66.25,62.8 66.25,59.54 66.64,59.14 v2(66.64,58.95)
  BOTTOM w0.483: R186.1 v1(50.73,100.67)
I2C_SDA_PPORT: length 79
  TOP w0.127: J2.24 48.44,72.64 47.37,72.64 45.97,71.25 45.97,62.11 38.86,55 38.86,54.99 31.75,47.88 31.75,37.34 30.1,35.69 25.39,35.69 24.13,34.43 ; 24.13,34.43 J45.3 ; 24.13,34.43 24.13,34.43 21.97,36.59 21.97,52.32 18.96,55.33 J77.86
I2S-MCLK: length 207.6
  TOP w0.127: v1(12.66,53.36) 12.66,53.37 13.62,54.33 J77.90
  TOP w0.381: v1(50.31,81.06) 50.25,81.06 49.76,80.57 49.76,78.98 49.15,78.37 J2.6
  TOP w0.483: R261.2 v1(72.19,73.02)
  SIG1#3 w0.127: v1(12.66,53.36) 11.48,52.18 6.82,52.18 0.89,58.11 0.89,76.22 11.88,87.22 11.88,87.22 22.53,97.88 22.54,97.88 25.15,100.48 39.14,100.48 43.81,105.15 43.81,105.15 45.53,106.87 45.53,106.87 48.8,110.15 48.8,115.1 49.75,116.05 63.53,116.05 64.69,114.88 64.69,110.84 66.8,108.73 66.8,108.73 70.25,105.28 75.42,105.28 76.19,104.51 76.19,102.1 75.57,101.47 J20.7 74.14,100.55 71.47,100.55 64.93,94.01 64.93,90.42 57.01,82.5 51.02,82.5 50.31,81.79 v1(50.31,81.06) 50.54,81.06 51.5,82.02 52.46,82.02 52.46,82.02 60.35,82.02 67.08,75.29 70.63,75.29 72.22,73.7 72.22,73.04 v1(72.19,73.02)
I2S_CLK: length 208
  TOP w0.127: v1(7.22,52.62) 7.43,52.83 J77.95
  TOP w0.381: J2.5 v1(40.42,78.37)
  TOP w0.483: R254.2 v1(67.11,73.02)
  SIG2#6 w0.127: v1(67.11,73.02) 58.06,82.07 44.12,82.07 v1(40.42,78.37) 40.42,99 43.67,102.25 54.64,102.25 56.4,104.01 69.97,104.01 J20.4 74.78,109.37 70.67,109.37 66.85,105.55 57,105.55 54.26,102.82 43.28,102.82 39.49,99.03 39.49,89.64 37.93,88.08 22.46,88.08 14.18,79.79 14.18,72.5 2.95,61.28 2.95,55.35 5.67,52.62 v1(7.22,52.62)
I2S_SD: length 217.3
  TOP w0.127: J77.93 v1(7.29,53.33)
  TOP w0.305: v1(46.55,83.01) 46.1,82.56 46.1,77.45 47.71,75.83 J2.14
  TOP w0.483: R255.2 68.13,72.83 v1(68.58,73.28)
  SIG1#3 w0.127: v1(68.58,73.28) 68.58,73.29 68.31,73.56 66.36,73.56 59.63,80.29 53.36,80.29 52.85,80.29 51.6,79.03 48.96,79.03 46.55,81.44 v1(46.55,83.01)
  SIG2#6 w0.127: v1(46.55,83.01) 44.91,83.01 40.88,87.04 40.88,98.84 43.81,101.78 54.78,101.78 56.51,103.5 72.01,103.5 J20.5 76.34,107.83 76.34,109.43 75.49,110.28 70.53,110.28 66.25,106 56.75,106 54,103.26 42.92,103.26 39,99.34 39,91.62 37.93,90.55 23.93,90.55 13.74,80.37 13.74,72.73 2.52,61.51 2.52,55.09 5.69,51.92 7.41,51.92 7.8,52.31 7.8,53 7.47,53.33 v1(7.29,53.33)
I2S_WP: length 203.7
  TOP w0.127: J77.91 v1(6.92,53.83)
  TOP w0.305: J2.18 47.76,74.56 v1(47.6,74.72)
  TOP w0.483: v1(65.08,73.1) R256.2
  SIG1#3 w0.127: v1(6.92,53.83) 6.92,53.86 1.32,59.46 1.32,76.04 12.06,86.79 12.07,86.79 25.2,99.92 39.19,99.92 43.99,104.72 43.99,104.72 51.38,112.11 51.38,115.01 51.99,115.62 63.35,115.62 64.26,114.7 64.26,110.56 65.91,108.91 65.91,108.9 70.06,104.76 74.31,104.76 J20.6 73.04,101.99 70.38,101.99 68.45,100.06 68.44,100.06 61.76,93.38 46.69,93.38 45.9,92.59 45.9,89.01 46.54,88.36 46.54,84.64 46.09,84.19 46.09,80.74 47.6,79.23 47.6,74.72 ; v1(65.08,73.1) 58.33,79.86 53.03,79.86 51.78,78.6 49.44,78.6 48.33,77.5 48.33,75.39 47.67,74.72 47.6,74.72 47.6,74.72 ; 47.6,74.72 v1(47.6,74.72)
INT_N_CTL15: length 89.2
  TOP w0.203: v1(12.89,68.47) 12.95,68.53 12.95,68.55 13.23,68.83 J77.52
  TOP w0.305: v1(58.45,60.67) 58.47,60.65 60.35,60.65 60.64,60.95 U1.L8
  TOP w0.381: J1.22 31.66,62.11 32.58,62.11 32.61,62.08 32.69,62.08 33.34,61.43 v1(33.34,60.42)
  SIG1#3 w0.127: v1(33.34,60.42) 33.34,59.66 33.48,59.52 33.48,58.85 34.33,58 45.96,58 46.76,58.81 46.77,58.81 48.49,60.53 52.34,60.53 53.56,61.74 57.35,61.74 58.42,60.67 v1(58.45,60.67)
  SIG2#6 w0.127: v1(33.34,60.42) 33.15,60.23 32.96,60.23 32.26,59.53 32.25,59.53 31.5,58.77 31.5,58.77 28.89,56.16 22.09,56.16 21.35,56.9 20.03,56.9 15.55,56.9 15.07,57.38 15.07,57.38 14.62,57.83 10.76,57.83 9.87,56.93 9.87,55.78 8.39,54.3 6.09,54.3 3.5,56.88 3.5,61.18 9.17,66.85 11.62,66.85 12.89,68.11 v1(12.89,68.47)
  BOTTOM w0.483: R170.1 58.56,60.78 v1(58.45,60.67)
N_SRST: length 5.2
  TOP w0.483: J51.15 17.86,28.65 R51.1
OTG_ID: length 53.6
  TOP w0.127: U1.C9 v2(67.44,59.75)
  TOP w0.381: 90.86,57.76 J48.4
  TOP w0.483: 90.86,57.76 90.75,57.76 89.51,59.01 v1(84.64,59.01)
  SIG2#6 w0.127: J50.1 69.98,39.54 84.64,54.21 v1(84.64,59.01) 70.34,59.01 68.98,60.37 67.86,60.37 67.44,59.95 v2(67.44,59.75)
PCLK: length 74.6
  TOP w0.203: J77.44 16.55,70.83 17.26,70.13 17.26,70.11 v1(17.37,70.01)
  TOP w0.381: v1(25.8,67.45) 25.79,67.45 25.52,67.17 24.58,67.17 J1.5
  SIG1#3 w0.127: v1(17.37,70.01) 17.37,69.63 17.78,69.21 19.31,69.21 19.94,69.84 19.94,73.34 16.77,76.5 16.77,78.98 18.05,80.26 22.62,80.26 25.42,77.46 25.42,72.34 27.07,70.69 27.07,68.01 26.52,67.46 25.89,67.46 25.88,67.45 v1(25.8,67.45)
  SIG2#6 w0.127: v1(25.8,67.45) 25.8,67.48 25.25,68.03 25.25,68.76 25.8,69.32 25.81,69.32 26.57,70.08 29.48,70.08 29.57,69.99 33.58,69.99 36.06,67.51 42.63,67.51 43.14,67 43.29,66.99 48.24,66.99 49.4,68.15 51.07,68.15 52.7,66.52 52.71,66.52 53.06,66.17 53.94,66.17 v1(53.94,66.17)
  BOTTOM w0.483: R220.2 54.32,66.55 v1(53.94,66.17)
PMODE0_CON: length 21.3
  TOP w0.254: J77.36 16.17,72.83 v1(16.18,72.84)
  SIG2#6 w0.127: v1(16.18,72.84) 16.18,73.31 16.51,74.07 16.79,74.73 16.98,75.1 26.92,85.04 26.92,86.2 27.6,86.87 28.8,86.87 J96.1
PMODE1_CON: length 31.5
  TOP w0.203: v1(16.15,70.29) 16.1,70.33 J77.46
  SIG2#6 w0.127: J97.1 34.82,86.87 35.04,86.65 35.04,85.87 34.74,85.57 28.25,85.57 17.15,74.46 16.9,73.89 16.9,71.04 v1(16.15,70.29)
PMODE2_CON: length 30.3
  TOP w0.254: v1(17.87,74.39) 17.75,74.39 17.71,74.35 17.23,74.35 17.22,74.33 J77.30
  SIG2#6 w0.127: v1(17.87,74.39) 17.93,74.39 18.4,74.86 28.67,85.14 37.88,85.14 38.31,85.57 38.31,86.52 38.09,86.74 J98.1
PMODE_0: length 44.2
  TOP w0.483: v1(50.36,75.29) 50.73,74.93 R234.2
  SIG1#3 w0.127: J96.2 32.51,93.11 37.9,93.11 38.96,92.05 38.96,74.41 39.12,74.25 39.82,73.55 41.62,73.55 41.98,73.55 42.27,73.27 42.27,73.27 42.63,72.9 48.56,72.9 49.74,74.08 49.74,74.09 50.36,74.71 v1(50.36,75.29)
PMODE_0_DIP: length 20.6
  TOP w0.483: SW25.1 R7.1 v1(21.77,106.62)
  SIG2#6 w0.127: J96.3 26.92,93.83 26.92,100.84 22.35,105.41 22.35,106.04 v1(21.77,106.62)
PMODE_1: length 35.5
  TOP w0.483: R235.2 50.69,73.15 50.57,73.28 v1(50.56,73.28)
  SIG1#3 w0.127: J97.2 34.09,90.42 37.83,90.42 38.52,89.73 38.52,74.23 39.42,73.34 39.64,73.12 41.8,73.12 42.09,72.84 42.09,72.84 42.45,72.47 48.74,72.47 49.55,73.28 v1(50.56,73.28)
PMODE_1_DIP: length 21.8
  TOP w0.483: SW25.2 R8.1 v1(23.08,106.62)
  SIG2#6 w0.127: J97.3 33.07,95.96 23.5,105.54 23.5,106.17 23.08,106.59 v1(23.08,106.62)
PMODE_2: length 43.6
  TOP w0.483: v1(54.12,71.26) 54.39,70.99 R236.2
  SIG1#3 w0.127: J98.2 33.45,85.4 33.45,77.14 38.86,71.73 38.86,71.72 39.51,71.07 39.51,68.95 42.89,65.57 45.62,65.57 46.19,66.14 46.19,66.14 46.48,66.43 46.48,66.43 47.33,67.28 47.34,67.28 47.59,67.54 47.6,67.54 49.12,69.06 50.91,69.06 52.28,70.43 53.13,70.43 53.13,70.43 53.2,70.43 54.03,71.26 v1(54.12,71.26)
PMODE_2_DIP: length 23.2
  TOP w0.483: v1(24.34,106.62) R19.1 SW25.3
  SIG2#6 w0.127: v1(24.34,106.62) 37.34,93.62 J98.3
REG_VBATT:
  vias: v3(32.85,30.87) v3(33.71,29.95)
RESET_N: length 138.4
  TOP w0.127: U1.C5 67.24,63.54 67.24,63.54 v2(67.44,63.75)
  TOP w0.381: v1(31.58,54.27) 31.58,56.95 J1.38
  TOP w0.508: R10.1 11.75,100.9 J72.2
  SIG1#3 w0.127: v2(67.44,63.75) 66.87,63.17 66.06,63.17 65.45,62.56 65.45,60.4 65.08,60.03 65.08,53.23 63.17,51.32 34.53,51.32 31.58,54.27 v1(31.58,54.27)
  SIG2#6 w0.127: J72.2 9.91,98.93 9.91,95.79 1.41,87.29 1.41,55.08 6.77,49.72 27.04,49.72 31.58,54.26 v1(31.58,54.27)
RESET_N_CON: length 35.7
  TOP w0.279: v1(6.63,67.29) 6.63,67.29 7.09,66.83 J77.59
  SIG2#6 w0.127: J72.3 11.81,94.87 6.61,89.67 6.61,67.31 v1(6.63,67.29)
RESET_SWITCH: length 13.5
  TOP w0.483: SW8.B1 SW8.B2
  TOP w0.508: J72.1 12.64,104.21 R63.1 C1.1 12.64,109.62 SW8.B1
RS232_CTS_OUT: length 8.8
  TOP w0.483: J38.7 88.44,96.77 86.31,94.64 84.46,94.64 82.96,96.14 R27.1
RS232_RTS_IN: length 10.5
  TOP w0.483: J38.8 88.44,94.14 86.18,91.87 83.19,91.87 81.73,93.33 R33.1
RS232_RX_IN: length 10.4
  TOP w0.483: J38.3 87,97.42 87,99.44 86.25,100.19 83.75,100.19 R29.1
RS232_TX_OUT: length 4.6
  TOP w0.483: R25.1 81.8,97.09 83.76,97.09 85.47,98.79 J38.2
RTCK: length 6.5
  TOP w0.483: J52.2 18.11,23.83 J51.11
SPI-MISO_UART-TX: length 45.2
  TOP w0.305: v1(48.42,81.13) 48.42,80.93 47.2,79.71 47.2,77.72 47.82,77.1 J2.10
  TOP w0.483: R259.2 v1(70.16,73.02)
  SIG1#3 w0.127: v1(70.16,73.02) 70.17,73.02 70.17,73.76 69.51,74.42 66.72,74.42 59.99,81.15 52.83,81.15 52.83,81.15 52.5,81.15 51.24,79.9 49.66,79.9 48.43,81.13 v1(48.42,81.13) 48.42,81.23 48.34,81.31 48.34,83.84 50.17,85.66 50.17,90.57 51.8,92.2 J103.2
SPI-MOSI_UART-RX: length 44.9
  TOP w0.381: J2.8 49.63,77.74 50.47,78.58 v1(50.47,80.34)
  TOP w0.483: R260.2 v1(71.18,73.02)
  SIG1#3 w0.127: v1(71.18,73.02) 71.18,73.39 69.72,74.85 66.9,74.85 60.17,81.59 52.28,81.59 51.04,80.34 v1(50.47,80.34) 50.4,80.34 49.53,81.2 49.53,83.82 54.96,89.25 54.96,90.79 56.37,92.2 J104.2
SPI-SCK_UART-RTS: length 45.2
  TOP w0.305: J2.16 48.4,75.25 47.61,75.25 47.22,75.64 v1(47.14,75.64)
  TOP w0.483: R257.2 v1(66.1,73.1)
  SIG1#3 w0.127: J101.2 42.69,92.2 43.89,91 43.89,88.14 43.19,87.44 43.19,82.89 47.12,78.95 47.12,75.96 47.13,75.96 47.13,75.78 47.14,75.77 v1(47.14,75.64)
  SIG2#6 w0.127: v1(47.14,75.64) 47.15,75.64 51.81,80.31 59.13,80.31 66.1,73.34 v1(66.1,73.1)
SPI-SSN_UART-CTS: length 45
  TOP w0.305: v1(47.72,81) 46.64,79.92 46.64,77.65 47.82,76.47 J2.12
  TOP w0.483: R258.2 v1(69.15,73.02)
  SIG1#3 w0.127: v1(69.15,73.02) 69.15,73.53 68.69,73.99 66.54,73.99 59.81,80.72 53.01,80.72 52.67,80.72 51.42,79.46 49.26,79.46 v1(47.72,81) 47.72,84.59 48.7,85.57 48.7,90.79 47.29,92.2 J102.2
SPI_CLK: length 37.3
  TOP w0.127: R61.1 60.38,110.94 60.06,111.26 58.61,111.26 v1(58.29,110.94)
  SIG1#3 w0.127: J101.3 45.19,94.74 49.36,98.91 50.86,98.91 57.44,105.49 57.44,110.09 v1(58.29,110.94)
  SIG2#6 w0.127: J34.3 53.66,110.93 58.29,110.93 v1(58.29,110.94)
SPI_CLK_FLASH: length 3.8
  TOP w0.127: U26.6 v1(60.71,109.23) R61.2
  BOTTOM w0.483: R61.2 v1(60.71,109.23)
SPI_HOLD#_FLASH: length 3
  TOP w0.127: R248.2 59.44,109.91 U26.7
SPI_MISO: length 28.7
  TOP w0.127: R60.1 v1(60.27,96.96)
  SIG1#3 w0.127: J34.6 60.07,112.14 60.07,97.15 v1(60.27,96.96) 60.27,96.96 59.31,96 53.07,96 J103.3
SPI_MISO_FLASH: length 3.8
  TOP w0.127: R60.2 v1(59.44,98.77) U26.2
  BOTTOM w0.483: v1(59.44,98.77) 59.49,98.71 59.49,97.92 R60.2
SPI_MOSI: length 34.9
  TOP w0.127: R59.1 v1(63.88,109.98)
  SIG1#3 w0.127: J104.3 59.86,94.74 62.54,97.42 62.54,108.56 63.88,109.9 v1(63.88,109.98)
  SIG2#6 w0.127: v1(63.88,109.98) 63.88,111 62.47,112.41 54.73,112.41 J34.4
SPI_MOSI_FLASH: length 3.8
  TOP w0.127: U26.5 v1(61.98,109.22) 62.03,109.28 R59.2
  BOTTOM w0.483: R59.2 62.03,109.28 v1(61.98,109.22)
SPI_SSN: length 30.6
  TOP w0.127: R62.1 v1(57.21,98.68)
  SIG1#3 w0.127: J102.3 50.42,97.92 56.45,97.92 v1(57.21,98.68) 57.22,98.68 58.96,100.41 58.96,111.09 55.63,114.43 55.24,114.43
SPI_SSN_FLASH: length 3.7
  TOP w0.127: R62.2 58.17,97.97 v1(58.17,98.75) U26.1
  BOTTOM w0.483: R62.2 58.11,98.69 v1(58.17,98.75)
SPI_WP#_FLASH: length 3.8
  TOP w0.127: R250.2 60.64,98.74 v1(60.71,98.81) U26.3
  BOTTOM w0.483: v1(60.71,98.81) 60.64,98.74 R250.2
SS_DM: length 24.6
  TOP w0.305: J48.2 arc(92.3,56.53) 92.19,56.55 84.34,56.55 arc(82.7,56.88) 81.3,57.81 arc(79.45,59.05) 77.26,59.48 68.96,59.48 arc(68.79,59.45) U1.A10
SS_DP: length 24.6
  TOP w0.305: U1.A9 arc(68.82,60.03) 69.03,59.99 77.26,59.99 arc(79.64,59.52) 81.66,58.17 arc(82.89,57.34) 84.34,57.06 92.26,57.06 arc(92.33,57.07) J48.3
SS_RX_M: length 24
  TOP w0.305: U1.A3 68.79,64.8 87.75,64.8 87.88,64.68 U9.6 U9.5 90.73,64.68 91.1,65.04 92.32,65.04 J48.10
SS_RX_P: length 24
  TOP w0.305: U1.A4 68.79,64.29 87.54,64.29 87.67,64.17 U9.7 U9.4 90.94,64.17 91.31,64.53 92.32,64.53 J48.9
SS_TX_M: length 20
  TOP w0.305: C46.2 72.84,62.7 U9.10 U9.1 90.23,62.7 90.33,62.6 92.31,62.6 J48.6
SS_TX_P: length 20
  TOP w0.305: J48.7 92.34,63.11 90.54,63.11 90.44,63.2 U9.2 U9.9 72.84,63.2 C43.2
TCK: length 74.4
  TOP w0.127: v2(64.24,62.15) 64.49,62.39 64.49,62.39 U1.F6
  TOP w0.483: J52.1 21.09,20.07 R52.1 17.22,18.87 J51.9
  SIG2#6 w0.127: J52.1 22.3,22.11 24.65,24.46 24.65,29.02 34.07,38.44 34.09,38.44 34.11,38.46 45.39,38.46 61.66,54.72 63.03,54.72 64.65,56.34 64.65,59.87 64.65,61.75 64.25,62.15 v2(64.24,62.15)
TDI: length 78.5
  TOP w0.127: U1.E7 v2(65.84,61.35)
  TOP w0.483: J51.5 R54.1 v1(21.09,15.26)
  SIG2#6 w0.127: v2(65.84,61.35) 65.84,61.35 65.44,60.95 65.44,60.38 65.03,59.98 65.03,56.18 63.19,54.34 61.89,54.34 45.57,38.02 34.29,38.02 33.19,36.93 33.17,36.93 25.08,28.84 25.08,24.56 25.08,24.56 25.08,24.28 24.03,23.23 24.03,21.31 20.37,17.64 20.37,16.16 21.09,15.44 v1(21.09,15.26)
TDO: length 74.6
  TOP w0.127: U1.C10 v2(67.44,58.95)
  SIG1#3 w0.127: J51.13 17.54,24.71 18.03,25.2 34.34,25.2 42.36,33.23 42.53,33.4 43.05,33.4 45.82,36.17 45.82,36.55 48.68,39.41 59.59,39.41 69.05,48.88 69.05,58.1 68.6,58.55 67.84,58.55 v2(67.44,58.95)
TMS: length 75.2
  TOP w0.127: U1.E8 v2(65.84,60.55)
  TOP w0.483: J51.7 R53.1 v1(21.09,17.67)
  SIG2#6 w0.127: v1(21.09,17.67) 21.09,17.67 22.03,17.67 24.47,20.11 24.47,23.05 25.51,24.1 25.51,24.26 25.52,24.27 25.52,28.64 34.47,37.59 45.75,37.59 62.12,53.96 63.35,53.96 65.41,56.03 65.41,56.34 65.41,58 65.31,58.1 65.31,59.5 65.84,60.04 v2(65.84,60.55)
TRST_N: length 81.7
  TOP w0.127: U1.B11 v2(68.24,58.15)
  TOP w0.483: v1(21.09,11.06) R55.1 J51.3
  SIG2#6 w0.127: v2(68.24,58.15) 68.25,58.15 69.5,56.9 69.5,51.38 55.58,37.46 51.67,37.46 43.54,29.33 34.01,29.33 24.91,20.24 24.91,18.2 21.09,14.38 21.09,11.06 v1(21.09,11.06)
U3RX_VDDQ: length 1.1
  TOP w0.254: v2(69.6,65.51) 69.36,65.75 U1.A2
U3TX_VDDQ: length 3.7
  TOP w0.254: U1.B5 67.65,63.16 67.65,63.16 v2(67.44,62.95)
  BOTTOM w0.381: C104.1 67.34,62.84 v2(67.44,62.95) 68.76,64.26 C105.1
  vias: v2(71.71,67.59) v2(71.86,68.65) v2(71.86,68.12)
UART_CTS: length 14.5
  TOP w0.254: v1(58.72,91.63) 58.84,91.52 60.77,91.52 U7.3
  SIG2#6 w0.127: v1(58.72,91.63) 58.03,90.93 48.53,90.93 47.26,89.66 J102.1
UART_CTS_LT: length 12.6
  TOP w0.432: U7.12 67.44,91.58 68.59,92.74 v1(68.59,93.42)
  BOTTOM w0.483: v1(68.59,93.42) 68.59,94.17 70.31,95.89 75.38,95.89 R26.2
UART_FORCE_OFF: length 3.2
  TOP w0.254: R35.2 R31.1 72.24,90.48 72.81,91.06 73.27,91.06 U6.20
UART_FORCE_ON: length 2.7
  TOP w0.432: U6.14 73.97,94.96 v3(74.1,94.83)
  BOTTOM w0.483: v3(74.1,94.83) 74.12,94.81 R34.2 R30.1
UART_READY: length 2.8
  TOP w0.305: U6.1 78.39,91.05 v3(78.26,90.93)
  BOTTOM w0.483: v3(78.26,90.93) 78.2,90.99 R23.2 76.45,90.99 R22.1
UART_RTS: length 20.2
  TOP w0.254: v1(59.54,92.94) 59.65,92.83 59.65,92.83 60.24,92.23 U7.2
  SIG2#6 w0.127: v1(59.54,92.94) 59.05,93.42 46.43,93.42 42.67,89.66 J101.1
UART_RTS_LT: length 5.8
  TOP w0.305: 67.83,93.39 67.83,92.77 67.29,92.23 U7.13
  TOP w0.432: 67.83,93.39 67.83,93.74 69.72,95.63 R32.2
UART_RX: length 4.7
  TOP w0.381: J104.1 59.03,89.66 59.65,90.28 U7.5
UART_RX_LT: length 5.7
  TOP w0.432: U7.10 68.05,90.28 70.54,92.77 R28.2
UART_TX: length 10.5
  TOP w0.381: U7.4 v1(59.7,90.93)
  SIG2#6 w0.127: v1(59.7,90.93) 59.69,90.93 57.28,88.52 52.96,88.52 J103.1
UART_TX_LT: length 6.2
  TOP w0.432: U7.11 67.78,90.93 69.38,92.53 69.38,93.93 70.06,94.61 R24.2
USB3_VBUS: length 40.3
  TOP w0.254: 65.44,57.82 U1.E11
  TOP w0.381: 65.41,57.78 65.44,57.82
  TOP w0.508: 72.69,25.91 U37.5
  TOP w0.635: 65.41,57.78 65.38,57.78 64.46,56.87 64.46,39.04 67.36,36.15 67.36,27.65 69.09,25.91 72.69,25.91 C186.1
USB_DRV_VBUS: length 171.4
  TOP w0.33: 82.4,37.38 82.4,42.18 TP46.1 ; 82.4,37.38 R264.1 ; 82.4,37.38 U8.1
  TOP w0.635: U45.4 v3(22,98.52)
  SIG2#6 w0.762: TP46.1 81.15,43.43 81.15,49.29 85.78,53.92 85.78,62.3 81.37,66.71 81.37,71.41 75.78,77 75.78,88.67 76.85,89.74 78.32,89.74 79.97,91.39 79.97,117.03 77.93,119.07 23.69,119.07 20.26,115.63 20.26,101.79 21.97,100.08 21.97,98.55 v3(22,98.52)
VIO1: length 2.6
  TOP w0.254: U1.H11 62.89,58.4 62.89,58.4 v2(62.64,58.15) ; U1.L9 60.64,59.99 60.59,59.94 60.59,59.91 v2(60.45,59.77)
  BOTTOM w0.406: v2(60.45,59.77) 59.99,59.77 59.93,59.72 C88.1 59.75,59.87 R170.2
  vias: v3(17.89,101.75) v3(18.67,101.75) v3(18.83,102.99) v3(21.74,105.69) v3(22.99,105.68) v3(24.22,105.7)
